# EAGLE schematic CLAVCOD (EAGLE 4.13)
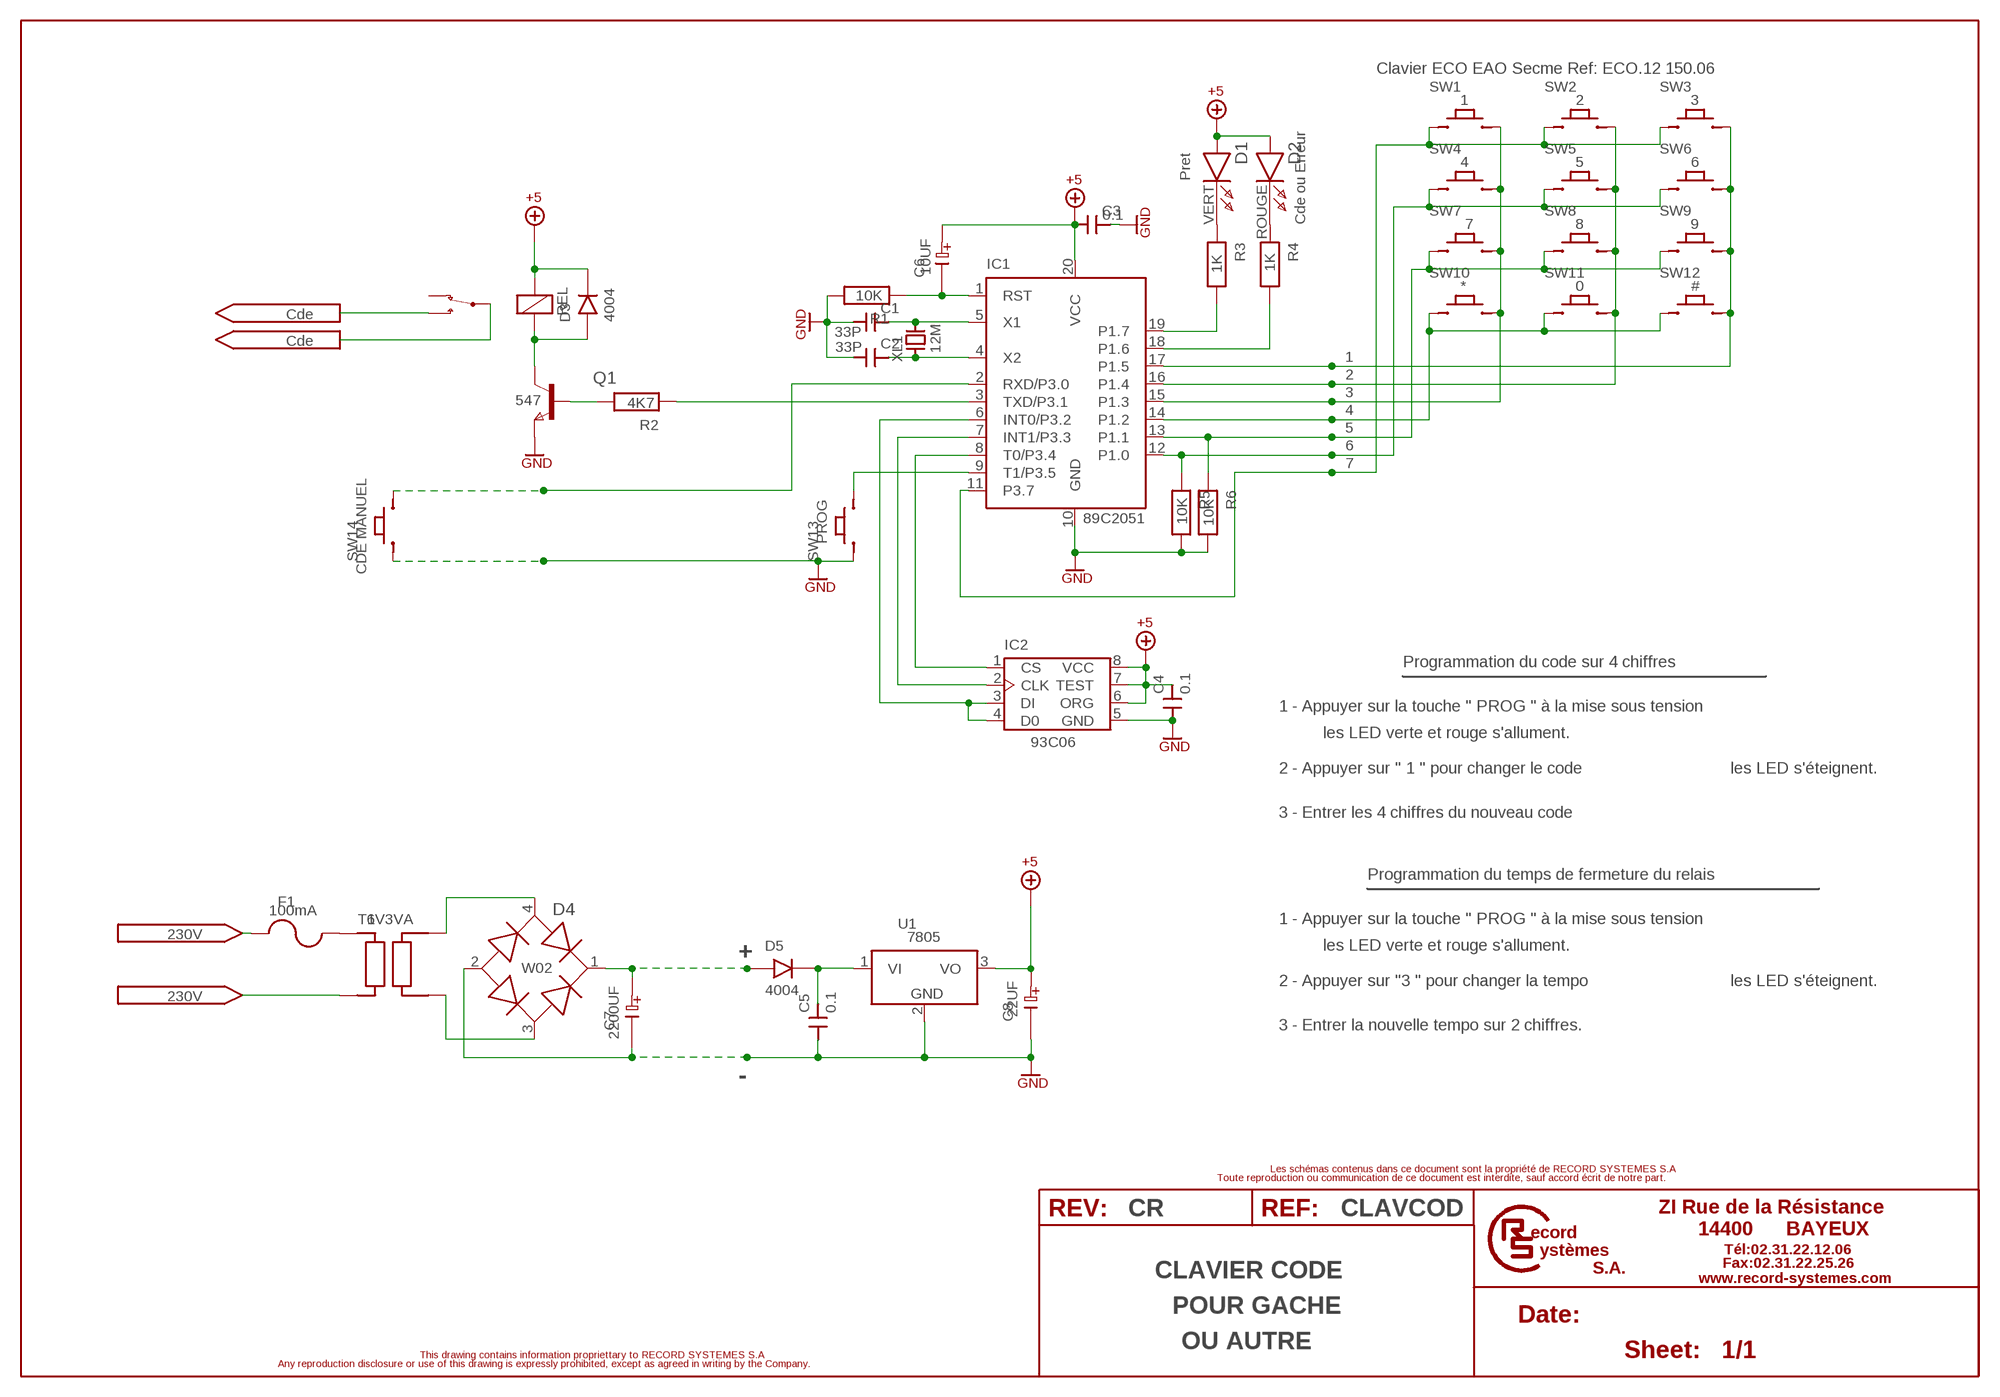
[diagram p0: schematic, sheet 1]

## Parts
C1  33P  C5  [C5]
C2  33P  C5  [C5]
C3  0.1  C5  [C5]
C4  0.1  C5  [C5]
C5  0.1  C5  [C5]
C6  10UF  E5  [E5]
C7  2200UF  E5  [E5]
C8  22UF  E5  [E5]
D1  VERT  LED  [LED+H]
D2  ROUGE  LED  [LED+H]
D3  4004  D5  [D5]
D4  W02  [W02]
D5  4004  D5  [D5]
F1  100mA  FUSE2  [FUSE2]
IC1  89C2051  [DIL20]
IC2  93C06  [DIL8]
K1  REL  E3206S  [E3206S]
PRT1  230V  PRTINPRT  [PRT]
PRT2  230V  PRTINPRT  [PRT]
Q1  547  BC547  [T1]
R1  10K  R5  [R5]
R2  4K7  R5  [R5]
R3  1K  R5  [R5]
R4  1K  R5  [R5]
R5  10K  R5  [R5]
R6  10K  R5  [R5]
SW1  1  COSMOS  [COSMOS]
SW2  2  COSMOS  [COSMOS]
SW3  3  COSMOS  [COSMOS]
SW4  4  COSMOS  [COSMOS]
SW5  5  COSMOS  [COSMOS]
SW6  6  COSMOS  [COSMOS]
SW7  7  COSMOS  [COSMOS]
SW8  8  COSMOS  [COSMOS]
SW9  9  COSMOS  [COSMOS]
SW10  *  COSMOS  [COSMOS]
SW11  0  COSMOS  [COSMOS]
SW12  #  COSMOS  [COSMOS]
SW13  PROG  COSMOS  [COSMOS]
SW14  CDE MANUEL  COSMOS  [COSMOS]
T1  6V3VA  T600  [T600]
U1  7805  78XXT  [TO-220A]
U$20  Cde  PRTOUTPRT  [PRT]
U$21  Cde  PRTOUTPRT  [PRT]
XL1  12M  QS  [QS]

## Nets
1: IC1.17(P1.5) SW3.2 SW6.2 SW9.2 SW12.2
2: IC1.16(P1.4) SW2.2 SW5.2 SW8.2 SW11.2
3: IC1.15(P1.3) SW1.2 SW4.2 SW7.2 SW10.2
4: IC1.14(P1.2) SW10.1 SW11.1 SW12.1
5: IC1.13(P1.1) R6.1 SW7.1 SW8.1 SW9.1
6: IC1.12(P1.0) R5.1 SW4.1 SW5.1 SW6.1
7: IC1.11(P3.7) SW1.1 SW2.1 SW3.1
+5 [alimgros]: C3.1 C4.2 C6.+ C8.+ D1.-(A) D2.-(A) D3.K IC1.20(VCC) IC2.6(ORG) IC2.7(TEST) IC2.8(VCC) K1.1 U1.3(VO)
GND [alimgros]: C1.1 C2.1 C3.2 C4.1 C5.1 C7.- C8.- D4.2 IC1.10(GND) IC2.5(GND) Q1.E R1.2 R5.2 R6.2 SW13.1 SW14.1 U1.2(GND)
N$1 [alimgros]: C1.2 IC1.5(X1) XL1.2
N$2 [alimgros]: C2.2 IC1.4(X2) XL1.1
N$3 [alimgros]: IC1.9(T1/P3.5) SW13.2
N$4 [alimgros]: C6.- IC1.1(RST) R1.1
N$5 [alimgros]: IC1.2(RXD/P3.0) SW14.2
N$6 [alimgros]: Q1.B R2.2
N$7 [alimgros]: IC1.3(TXD/P3.1) R2.1
N$8 [alimgros]: D4.4 T1.3
N$9 [alimgros]: IC1.6(INT0/P3.2) IC2.3(DI) IC2.4(D0)
N$10 [alimgros]: D3.A K1.2 Q1.C
N$11 [alimgros]: K1.S(2:S) U$20.1
N$12 [alimgros]: IC1.8(T0/P3.4) IC2.1(CS)
N$13 [alimgros]: IC1.7(INT1/P3.3) IC2.2(CLK)
N$14: D1.+(K) R3.1
N$15: D2.+(K) R4.1
N$16 [alimgros]: IC1.19(P1.7) R3.2
N$17 [alimgros]: IC1.18(P1.6) R4.2
N$18 [alimgros]: K1.P(2:P) U$21.1
N$19 [alimgros]: D4.3 T1.4
N$20: F1.2 T1.2
N$21 [alimgros]: F1.1 PRT1.1
N$22 [alimgros]: PRT2.1 T1.1
N$24 [alimgros]: C5.2 D5.K U1.1(VI)
N$26 [alimgros]: C7.+ D4.1 D5.A
Unconnected: K1.O(2:O)

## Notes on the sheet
- Clavier ECO EAO Secme Ref: ECO.12 150.06
- Pret
- Cde ou Erreur
- Programmation du code sur 4 chiffres
- 1 - Appuyer sur la touche " PROG " à la mise sous tension
- les LED verte et rouge s'allument.
- 2 - Appuyer sur " 1 " pour changer le code | les LED s'éteignent.
- 3 - Entrer les 4 chiffres du nouveau code
- Programmation du temps de fermeture du relais
- 1 - Appuyer sur la touche " PROG " à la mise sous tension
- les LED verte et rouge s'allument.
- +
- 2 - Appuyer sur "3 " pour changer la tempo | les LED s'éteignent.
- 3 - Entrer la nouvelle tempo sur 2 chiffres.
- -
- CR | CLAVCOD
- CLAVIER CODE
- POUR GACHE
- OU AUTRE

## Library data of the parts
C1-C5 = RECORD:C5
C6-C8 = RECORD:E5
D1 D2 = RECORD:LED
D3 D5 = RECORD:D5
D4 = RECORD:W02
F1 = RECORD:FUSE2
IC1 = ATMEL:89C2051
IC2 = RECORD:93C06
K1 = RELAIS:E3206S
PRT1 PRT2 = PORT:PRTIN: PORT IN
Q1 = RECORD:BC547
R1-R6 = RECORD:R5
SW1-SW14 = RECORD:COSMOS
T1 = RECORD:T600
U1 = LINEAR:78XXT
U$20 U$21 = PORT:PRTOUT: PORT OUT
XL1 = RECORD:QS

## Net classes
0 signal: width 0.4 mm, drill 0.4 mm, clearance 0.4 mm
1 siggros: width 0.8 mm, drill 0.6 mm, clearance 0.4 mm
2 alim: width 1 mm, drill 1 mm, clearance 0.4 mm
3 alimgros: width 1.27 mm, drill 1 mm, clearance 0.4 mm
